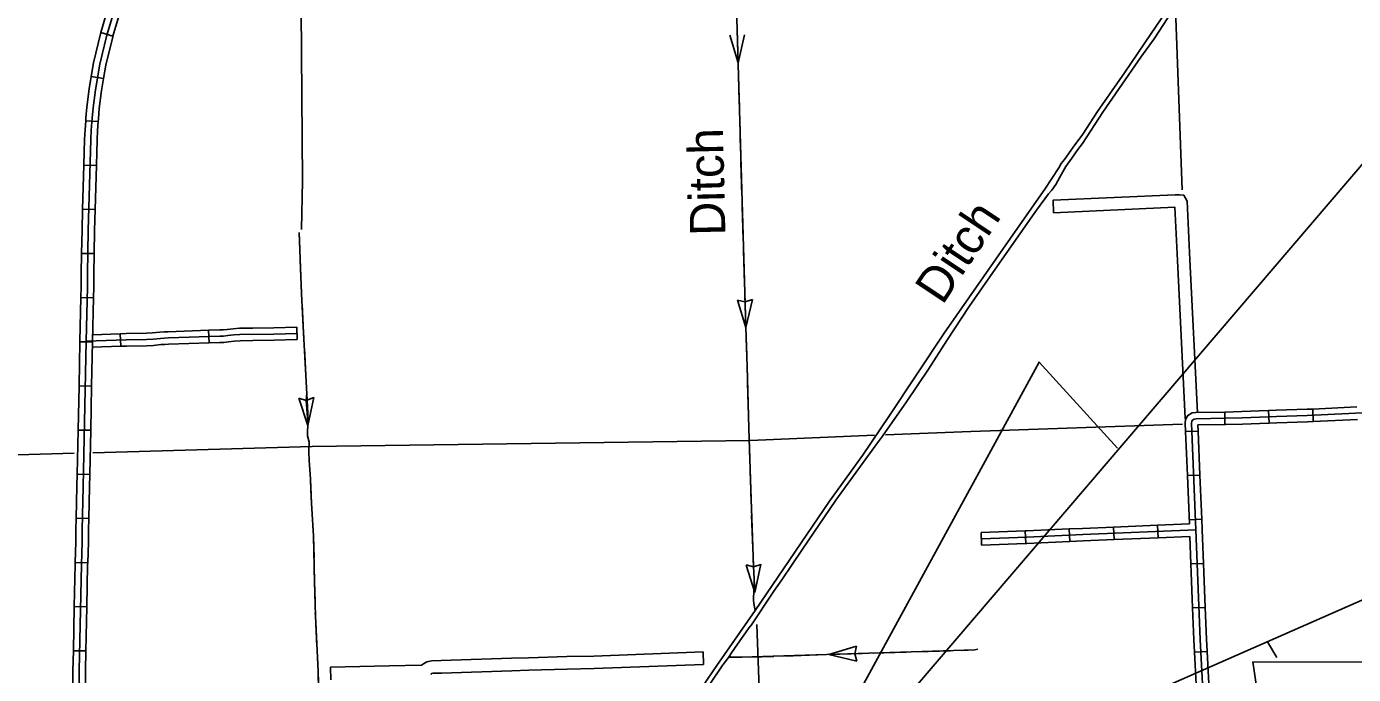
# Model space of a CAD drawing. Extents: x -5566 to 1759129, y -3726 to 731467.
# Drawn here: x -4880.9 to -4760.4, y 330.8 to 389.7 of the extents above; entities that cross this region are included whole.
import ezdxf

# ---------------------------------------------------------------- set-up
doc = ezdxf.new("R2010")
doc.units = 0
doc.layers.add('Default', color=7, linetype='Continuous')

msp = doc.modelspace()

# ---------------------------------------------------------------- linework, layer by layer
at = {"layer": 'Default'}
for p, q in [((-4874.16, 389.13), (-4873.07, 388.81)), ((-4816.32, 386.38), (-4817.06, 388.88)), ((-4816.32, 386.38), (-4815.72, 388.92)), ((-4875.04, 385.15), (-4873.92, 384.96)), ((-4875.55, 381.12), (-4874.41, 381.04)), ((-4875.71, 377.09), (-4874.57, 377.06)), ((-4875.83, 373.08), (-4874.69, 373.05)), ((-4875.93, 369.07), (-4874.79, 369.05)), ((-4875.98, 365.06), (-4874.85, 365.04)), ((-4815.62, 362.33), (-4816.36, 364.83)), ((-4816.36, 364.83), (-4815.69, 364.67)), ((-4815.02, 364.87), (-4815.68, 364.67)), ((-4815.62, 362.33), (-4815.02, 364.87)), ((-4872.41, 361.78), (-4872.37, 360.64)), ((-4864.4, 362.09), (-4864.35, 360.95)), ((-4856.38, 362.38), (-4856.35, 361.24)), ((-4876.07, 361.05), (-4874.93, 361.03)), ((-4876.15, 357.04), (-4875.01, 357.02)), ((-4856.19, 355.91), (-4855.52, 355.72)), ((-4855.39, 353.43), (-4856.19, 355.91)), ((-4854.84, 355.98), (-4855.52, 355.72)), ((-4855.39, 353.43), (-4854.84, 355.98)), ((-4772.12, 353.52), (-4772.13, 354.66)), ((-4768.09, 353.66), (-4768.15, 354.8)), ((-4764.09, 353.81), (-4764.14, 354.94)), ((-4876.23, 353.03), (-4875.09, 353.01)), ((-4774.54, 352.94), (-4775.68, 352.89)), ((-4876.31, 349.02), (-4875.17, 349)), ((-4774.38, 348.94), (-4775.51, 348.89)), ((-4876.41, 345.02), (-4875.27, 344.99)), ((-4774.21, 344.93), (-4775.35, 344.88)), ((-4794.2, 342.58), (-4794.25, 343.72)), ((-4790.2, 342.73), (-4790.24, 343.87)), ((-4786.19, 342.91), (-4786.24, 344.05)), ((-4782.18, 343.08), (-4782.23, 344.22)), ((-4778.18, 343.24), (-4778.22, 344.38)), ((-4876.5, 341.01), (-4875.36, 340.98)), ((-4815.59, 340.78), (-4814.91, 340.62)), ((-4814.78, 338.29), (-4815.59, 340.77)), ((-4814.24, 340.83), (-4814.9, 340.62)), ((-4814.78, 338.29), (-4814.24, 340.84)), ((-4774.07, 340.92), (-4775.21, 340.88)), ((-4876.59, 337), (-4875.45, 336.97)), ((-4773.9, 336.92), (-4775.04, 336.87)), ((-4876.67, 332.99), (-4875.53, 332.97)), ((-4808.06, 332.64), (-4805.56, 333.39)), ((-4808.06, 332.64), (-4805.52, 332.04)), ((-4805.56, 333.39), (-4805.72, 332.72)), ((-4805.52, 332.04), (-4805.72, 332.71)), ((-4773.72, 332.91), (-4774.86, 332.86))]:
    msp.add_line(p, q, dxfattribs=at)
for points in [[(-4813.76, 313.86), (-4581.46, 585.64), (-4581.46, 585.64)], [(-4813.97, 313.69), (-4397.1, 497.07), (-4397.1, 497.07)], [(-4817.67, 431.97), (-4816.9, 405.91), (-4816.49, 392.49), (-4815.62, 362.39), (-4815.53, 359.66), (-4815.5, 358.79), (-4815.34, 353.2), (-4815.17, 347.64), (-4814.91, 340.66), (-4814.85, 339.52), (-4814.9, 337.55), (-4814.88, 337.3), (-4814.8, 336.8), (-4814.76, 336.65)], [(-4872.85, 392.98), (-4873.29, 391.9), (-4873.71, 390.67), (-4874.16, 389.13)], [(-4871.8, 392.55), (-4872.22, 391.51), (-4872.62, 390.32), (-4873.07, 388.81)], [(-4873.16, 390.5), (-4873.64, 388.88), (-4874.27, 386.26), (-4874.67, 383.93), (-4874.88, 382.3), (-4874.96, 381.34), (-4875.04, 380.26), (-4875.08, 379.41), (-4875.31, 371.16), (-4875.39, 367.22), (-4875.39, 366.04), (-4875.5, 361.1), (-4875.77, 347.88), (-4875.86, 343.98), (-4875.87, 342.87), (-4875.94, 340.79), (-4876.14, 331.19), (-4876.16, 328.64)], [(-4855.99, 391.19), (-4855.86, 375.67), (-4855.94, 371.24)], [(-4777.52, 390.96), (-4778.8, 389.04), (-4781.24, 385.48), (-4783.67, 381.97), (-4785.02, 379.91), (-4785.88, 378.71), (-4786.69, 377.59), (-4786.98, 377.24), (-4787.19, 376.84), (-4788.45, 374.91), (-4791.8, 370.14), (-4797.61, 361.83), (-4802.63, 354.25), (-4805.02, 350.71), (-4808, 346.58), (-4814.76, 336.65), (-4818.25, 331.66), (-4820.01, 329.08)], [(-4776.91, 391.07), (-4778.55, 388.55), (-4779.75, 386.89), (-4781.71, 384.06), (-4783.19, 381.89), (-4785.05, 379.06), (-4785.48, 378.51), (-4786.01, 377.71), (-4786.57, 376.97), (-4786.96, 376.26), (-4787.46, 375.33), (-4787.83, 374.8), (-4788.14, 374.47), (-4789.22, 373.01), (-4792.98, 367.63), (-4795.33, 364.25), (-4797.35, 361.15), (-4799.02, 358.57), (-4801.01, 355.59), (-4803.19, 352.47), (-4803.57, 351.98), (-4804.73, 350.41), (-4807.44, 346.65)], [(-4776, 374.84), (-4776.59, 391.26)], [(-4816.4, 389.39), (-4816.32, 386.38)], [(-4874.16, 389.13), (-4874.2, 389.02), (-4874.83, 386.38), (-4875.04, 385.15)], [(-4873.07, 388.81), (-4873.09, 388.73), (-4873.71, 386.15), (-4873.92, 384.96)], [(-4875.04, 385.15), (-4875.23, 384.02), (-4875.45, 382.36), (-4875.53, 381.38), (-4875.55, 381.12)], [(-4873.92, 384.96), (-4874.11, 383.85), (-4874.32, 382.24), (-4874.39, 381.3), (-4874.41, 381.04)], [(-4816.29, 385.38), (-4816.24, 383.87)], [(-4816.24, 383.87), (-4816.2, 382.37)], [(-4875.55, 381.12), (-4875.61, 380.29), (-4875.65, 379.43), (-4875.71, 377.09)], [(-4874.41, 381.04), (-4874.47, 380.23), (-4874.51, 379.39), (-4874.57, 377.06)], [(-4816.17, 381.37), (-4816.08, 378.36)], [(-4816.05, 377.36), (-4815.97, 374.36)], [(-4875.71, 377.09), (-4875.83, 373.08)], [(-4874.57, 377.06), (-4874.69, 373.05)], [(-4787.67, 372.76), (-4787.72, 373.9), (-4776.62, 374.4), (-4776.25, 374.39), (-4775.85, 374.37), (-4775.54, 373.82), (-4775.29, 368.49), (-4774.6, 354.63)], [(-4875.83, 373.08), (-4875.88, 371.17), (-4875.93, 369.07)], [(-4874.69, 373.05), (-4874.74, 371.15), (-4874.79, 369.05)], [(-4815.94, 373.35), (-4815.85, 370.35)], [(-4787.67, 372.76), (-4776.65, 373.26), (-4776.43, 368.44), (-4775.72, 354.1), (-4775.69, 354)], [(-4856.17, 370.96), (-4855.94, 365.4), (-4855.76, 361.87), (-4855.53, 357.43), (-4855.39, 354.55), (-4855.39, 353.81), (-4855.4, 352.5), (-4855.27, 351.93), (-4855.29, 351.02), (-4855.25, 350.3), (-4855.15, 348.56), (-4855.04, 346.4), (-4854.85, 343.39), (-4854.76, 339.27), (-4854.69, 336.17), (-4854.45, 331.09), (-4854.3, 325.98), (-4854.12, 319.85)], [(-4856.17, 370.96), (-4856.11, 369.45)], [(-4875.93, 369.07), (-4875.96, 367.23), (-4875.96, 366.05), (-4875.98, 365.06)], [(-4874.79, 369.05), (-4874.82, 367.22), (-4874.82, 366.04), (-4874.85, 365.04)], [(-4815.82, 369.35), (-4815.73, 366.34)], [(-4856.07, 368.45), (-4855.94, 365.45)], [(-4875.98, 365.06), (-4876.07, 361.11), (-4876.07, 361.05)], [(-4815.7, 365.34), (-4815.62, 362.39), (-4815.62, 362.33)], [(-4874.85, 365.04), (-4874.93, 361.09), (-4874.93, 361.03)], [(-4855.89, 364.45), (-4855.76, 361.87), (-4855.74, 361.44)], [(-4856.36, 361.81), (-4858.47, 361.75), (-4861.55, 361.7), (-4862.11, 361.67), (-4862.65, 361.61), (-4863.03, 361.56), (-4863.37, 361.56), (-4868.04, 361.39), (-4868.77, 361.35), (-4869.43, 361.28), (-4870.02, 361.26), (-4871.86, 361.23), (-4875.5, 361.1)], [(-4872.41, 361.78), (-4874.92, 361.69)], [(-4868.41, 361.94), (-4868.82, 361.92), (-4869.47, 361.85), (-4870.04, 361.83), (-4871.87, 361.8), (-4872.41, 361.78)], [(-4864.4, 362.09), (-4868.07, 361.96), (-4868.41, 361.94)], [(-4860.38, 362.29), (-4861.57, 362.27), (-4862.16, 362.23), (-4862.71, 362.17), (-4863.07, 362.13), (-4863.38, 362.13), (-4864.4, 362.09)], [(-4856.38, 362.38), (-4858.48, 362.32), (-4860.38, 362.29)], [(-4876.07, 361.05), (-4876.15, 357.04)], [(-4874.93, 361.03), (-4875.01, 357.02)], [(-4872.37, 360.64), (-4874.94, 360.55)], [(-4868.35, 360.8), (-4868.72, 360.79), (-4869.38, 360.71), (-4870.01, 360.69), (-4871.84, 360.66), (-4872.37, 360.64)], [(-4864.35, 360.95), (-4868.02, 360.82), (-4868.35, 360.8)], [(-4860.36, 361.15), (-4861.53, 361.13), (-4862.06, 361.1), (-4862.58, 361.04), (-4863, 360.99), (-4863.36, 360.99), (-4864.35, 360.95)], [(-4856.35, 361.24), (-4858.45, 361.18), (-4860.36, 361.15)], [(-4855.69, 360.44), (-4855.53, 357.44)], [(-4815.58, 361.33), (-4815.53, 359.83)], [(-4815.53, 359.83), (-4815.53, 359.66), (-4815.5, 358.79), (-4815.49, 358.32)], [(-4813.62, 314.02), (-4813.62, 314.02), (-4788.99, 359.2), (-4781.86, 351.37)], [(-4876.15, 357.04), (-4876.23, 353.03)], [(-4875.01, 357.02), (-4875.09, 353.01)], [(-4815.46, 357.32), (-4815.37, 354.32)], [(-4855.48, 356.44), (-4855.52, 355.72), (-4855.39, 353.81), (-4855.39, 353.43)], [(-4775.68, 352.89), (-4775.71, 353.65), (-4775.7, 353.99), (-4775.48, 354.36), (-4775.09, 354.58), (-4774.76, 354.63), (-4772.13, 354.66)], [(-4774.15, 329.98), (-4774.35, 334.01), (-4774.61, 340.11), (-4774.74, 343.96), (-4775.14, 353.65), (-4775.13, 353.83), (-4775.07, 353.94), (-4774.91, 354.03), (-4774.72, 354.06), (-4772.08, 354.1), (-4770.55, 354.13), (-4768.97, 354.19), (-4767.42, 354.27), (-4764.63, 354.35), (-4758.97, 354.61)], [(-4772.13, 354.66), (-4772.09, 354.66), (-4770.57, 354.7), (-4768.99, 354.76), (-4768.15, 354.8)], [(-4768.15, 354.8), (-4767.45, 354.84), (-4764.65, 354.92), (-4764.14, 354.94)], [(-4764.14, 354.94), (-4760.13, 355.13)], [(-4876.23, 353.03), (-4876.31, 349.02)], [(-4875.09, 353.01), (-4875.17, 349)], [(-4815.34, 353.31), (-4815.34, 353.2), (-4815.25, 350.31)], [(-4802.94, 352.59), (-4795.17, 352.91), (-4775.96, 353.56)], [(-4774.54, 352.94), (-4774.56, 353.49), (-4772.12, 353.52)], [(-4772.12, 353.52), (-4772.07, 353.53), (-4770.53, 353.56), (-4768.94, 353.62), (-4768.09, 353.66)], [(-4768.09, 353.66), (-4767.4, 353.7), (-4764.61, 353.78), (-4764.09, 353.81)], [(-4764.09, 353.81), (-4760.08, 353.99)], [(-4855.38, 352.43), (-4855.27, 351.93), (-4855.29, 351.02), (-4855.25, 350.3), (-4855.2, 349.44)], [(-4855, 351.54), (-4815.21, 352.08)], [(-4815.21, 352.08), (-4803.93, 352.55)], [(-4775.51, 348.89), (-4775.68, 352.89)], [(-4774.38, 348.94), (-4774.54, 352.94)], [(-4894.18, 350.41), (-4876.61, 350.92)], [(-4874.89, 350.97), (-4855, 351.54)], [(-4876.31, 349.02), (-4876.34, 347.89), (-4876.41, 345.02)], [(-4875.17, 349), (-4875.2, 347.87), (-4875.27, 344.99)], [(-4855.15, 348.44), (-4855.07, 346.93)], [(-4815.22, 349.31), (-4815.17, 347.64), (-4815.12, 346.3)], [(-4775.33, 344.5), (-4775.51, 348.89)], [(-4774.21, 344.93), (-4774.38, 348.94)], [(-4855.07, 346.93), (-4855.04, 346.4), (-4854.98, 345.43)], [(-4807.44, 346.65), (-4810.47, 342.2), (-4812.34, 339.43), (-4813.06, 338.4), (-4815.17, 335.26), (-4815.23, 335.21), (-4816.37, 333.58), (-4816.91, 332.81), (-4817.11, 332.46), (-4817.65, 331.77), (-4817.7, 331.71), (-4818.99, 329.78), (-4819.55, 329.04), (-4820.71, 327.31), (-4822.48, 324.82), (-4825.42, 320.58), (-4827.19, 317.97), (-4828.24, 316.46), (-4828.66, 315.92), (-4829.31, 314.91)], [(-4876.41, 345.02), (-4876.43, 343.99), (-4876.44, 342.88), (-4876.5, 341.01)], [(-4875.27, 344.99), (-4875.29, 343.98), (-4875.3, 342.86), (-4875.36, 340.98)], [(-4815.09, 345.3), (-4814.97, 342.29)], [(-4774.07, 340.92), (-4774.17, 343.98), (-4774.21, 344.93)], [(-4854.92, 344.43), (-4854.85, 343.39), (-4854.81, 341.43)], [(-4794.25, 343.72), (-4790.24, 343.87)], [(-4794.22, 343.15), (-4790.11, 343.3), (-4785, 343.53), (-4774.74, 343.96)], [(-4790.24, 343.87), (-4790.13, 343.87), (-4786.24, 344.05)], [(-4786.24, 344.05), (-4785.03, 344.1), (-4782.23, 344.22)], [(-4782.23, 344.22), (-4778.22, 344.38)], [(-4778.22, 344.38), (-4775.33, 344.5)], [(-4794.2, 342.58), (-4790.2, 342.73)], [(-4790.2, 342.73), (-4790.09, 342.73), (-4786.19, 342.91)], [(-4786.19, 342.91), (-4784.98, 342.96), (-4782.18, 343.08)], [(-4782.18, 343.08), (-4778.18, 343.24)], [(-4778.18, 343.24), (-4775.29, 343.36)], [(-4775.21, 340.88), (-4775.29, 343.36)], [(-4876.5, 341.01), (-4876.51, 340.81), (-4876.59, 337)], [(-4875.36, 340.98), (-4875.37, 340.78), (-4875.45, 336.97)], [(-4814.93, 341.29), (-4814.91, 340.66), (-4814.85, 339.52), (-4814.78, 338.29)], [(-4854.79, 340.43), (-4854.76, 339.27), (-4854.72, 337.42)], [(-4775.04, 336.87), (-4775.18, 340.09), (-4775.21, 340.88)], [(-4773.9, 336.92), (-4774.04, 340.13), (-4774.07, 340.92)], [(-4876.59, 337), (-4876.67, 332.99)], [(-4875.45, 336.97), (-4875.53, 332.97)], [(-4854.7, 336.42), (-4854.69, 336.17), (-4854.56, 333.41)], [(-4814.88, 337.29), (-4814.8, 336.8), (-4814.76, 336.65)], [(-4774.86, 332.86), (-4774.92, 333.98), (-4775.04, 336.87)], [(-4773.72, 332.91), (-4773.78, 334.03), (-4773.9, 336.92)], [(-4814.6, 335.36), (-4813.91, 316.29)], [(-4767.4, 332.37), (-4768.25, 333.8)], [(-4876.67, 332.99), (-4876.71, 331.2), (-4876.73, 328.97)], [(-4875.53, 332.97), (-4875.57, 331.18), (-4875.59, 328.96)], [(-4845.06, 331.68), (-4844.89, 331.8), (-4844.56, 331.99), (-4844.15, 332.08), (-4843.26, 332.09), (-4836.88, 332.31), (-4835.33, 332.35), (-4831.85, 332.46), (-4829.42, 332.5), (-4819.49, 332.88), (-4819.45, 331.74)], [(-4794.54, 333.12), (-4794.82, 333.06), (-4816, 332.39), (-4816.78, 332.41), (-4817.11, 332.46)], [(-4809.06, 332.61), (-4812.06, 332.51)], [(-4805.05, 332.73), (-4808.06, 332.64)], [(-4801.04, 332.86), (-4804.05, 332.77)], [(-4797.04, 332.99), (-4800.04, 332.89)], [(-4794.54, 333.12), (-4794.82, 333.06), (-4796.03, 333.02)], [(-4774.67, 328.85), (-4774.72, 329.95), (-4774.86, 332.86)], [(-4773.53, 328.91), (-4773.58, 330), (-4773.72, 332.91)], [(-4854.51, 332.41), (-4854.45, 331.09), (-4854.4, 329.41)], [(-4845.06, 331.68), (-4847.98, 331.62), (-4853.31, 331.5), (-4853.29, 330.36)], [(-4844.19, 330.84), (-4844.19, 330.88), (-4844.14, 330.91), (-4844.02, 330.94), (-4843.23, 330.95), (-4836.85, 331.17), (-4835.3, 331.21), (-4831.82, 331.32), (-4829.39, 331.37), (-4819.45, 331.74)], [(-4815.95, 332.39), (-4816, 332.39), (-4817.14, 332.42)], [(-4813.07, 332.48), (-4815.21, 332.41)]]:
    msp.add_lwpolyline(points, dxfattribs=at)
msp.add_lwpolyline([(-4769.57, 331.97), (-4769, 328.11), (-4769.25, 322.27), (-4768.74, 321.94), (-4767.77, 321.94), (-4767.77, 319.89), (-4759.68, 319.89), (-4759.3, 320.72), (-4759.42, 322.07), (-4759.23, 323.62), (-4758.52, 324.84), (-4758.07, 325.73), (-4757.43, 326.7), (-4757.05, 327.73), (-4756.73, 328.56), (-4756.15, 329.27), (-4756.02, 329.72), (-4756.28, 330.04), (-4758.27, 330.04), (-4757.82, 330.94), (-4757.75, 331.52), (-4758.02, 331.96)], close=True, dxfattribs=at)

# ---------------------------------------------------------------- texts
for rotation, p in [(91.3544, (-4817.46, 370.71)), (56.3322, (-4797.76, 364.3))]:
    msp.add_text('Ditch', height=3.205, rotation=rotation, dxfattribs=at).set_placement(p)

doc.saveas('drawing.dxf')
